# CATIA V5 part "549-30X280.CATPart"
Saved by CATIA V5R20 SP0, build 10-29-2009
Part number: 549-30X280
Definition: NONE
Nomenclature: 549-30X280
Source: Unknown
Description: 549-30X280
Bounding box of the stored display mesh (mm): x 0 to 240, y -17.5 to 17.5, z -17.5 to 17.5
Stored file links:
  C:\Users\Utente\Desktop\IO LAVORO\3D X SITO CF\X SITO\PLASTICA\549\549-30X280.CATPart
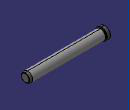
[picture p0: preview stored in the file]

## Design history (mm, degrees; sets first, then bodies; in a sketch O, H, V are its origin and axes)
Body1 "549-30X280" (main body)
  Solid1: solid without history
